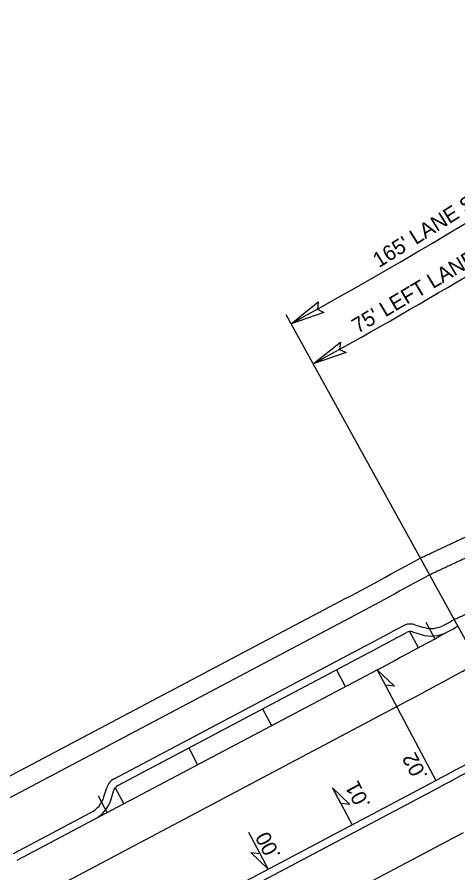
# Model space of a CAD drawing. Extents: x 1486489 to 1490134, y 497089 to 500876.
# Drawn here: x 1488009.9 to 1488126, y 498502.1 to 498727.6 of the extents above; entities that cross this region are included whole.
import ezdxf

# ---------------------------------------------------------------- set-up
doc = ezdxf.new("R2010")
doc.units = 0
for name, color, linetype in [('Prop Horizontal Alignment Station Label', 7, 'Continuous'), ('Scratch_Level_3', 7, 'Continuous'), ('Scratch_Level_5', 7, 'Continuous'), ('Sheet Block Title CELL', 7, 'Continuous'), ('Sheet Border Standard 30in CELL', 7, 'Continuous'), ('Sheet Cutting Line CELL', 7, 'Continuous'), ('Sheet Plot Border Outside CELL', 7, 'Continuous'), ('Sheet Sticker Exception Certification CELL', 7, 'Continuous'), ('Sheet Title CELL', 7, 'Continuous')]:
    doc.layers.add(name, color=color, linetype=linetype)

msp = doc.modelspace()

# ---------------------------------------------------------------- linework, layer by layer
at = {"layer": 'Prop Horizontal Alignment Station Label'}
for p, q in [((1487895.85, 498468.22), (1488095.16, 498573.73)), ((1487898.19, 498463.8), (1488097.5, 498569.31)), ((1488077.52, 498486.32), (1488127.44, 498512.75))]:
    msp.add_line(p, q, dxfattribs=at)
for radius in [1432.5, 1437.5]:
    msp.add_arc((1487424.96, 499839.79), radius, 297.89497, 298.84598, dxfattribs=at)
for points in [[(1488116.08, 498585.03), (1488116.74, 498585.34), (1488117.4, 498585.64), (1488118.05, 498585.95), (1488118.71, 498586.25), (1488119.36, 498586.56), (1488120.02, 498586.87), (1488120.67, 498587.17), (1488121.33, 498587.48), (1488121.98, 498587.79), (1488122.64, 498588.1), (1488123.29, 498588.4), (1488123.95, 498588.71), (1488124.6, 498589.02), (1488125.26, 498589.33), (1488125.91, 498589.64), (1488126.57, 498589.95), (1488127.22, 498590.26), (1488127.87, 498590.57), (1488128.53, 498590.88), (1488129.18, 498591.2), (1488129.83, 498591.51), (1488130.49, 498591.82), (1488131.14, 498592.13), (1488131.79, 498592.45), (1488132.45, 498592.76), (1488133.1, 498593.07), (1488133.75, 498593.39), (1488134.4, 498593.7), (1488135.06, 498594.01), (1488135.71, 498594.33), (1488136.36, 498594.65), (1488137.01, 498594.96), (1488137.66, 498595.28), (1488138.32, 498595.59), (1488138.97, 498595.91), (1488139.62, 498596.23), (1488140.27, 498596.54), (1488140.92, 498596.86), (1488141.57, 498597.18), (1488142.22, 498597.5), (1488142.87, 498597.82), (1488143.52, 498598.14), (1488144.18, 498598.46), (1488144.83, 498598.77), (1488145.48, 498599.09), (1488146.13, 498599.42), (1488146.78, 498599.74), (1488147.43, 498600.06), (1488148.07, 498600.38), (1488148.72, 498600.7), (1488149.37, 498601.02), (1488150.02, 498601.34), (1488150.67, 498601.67), (1488151.32, 498601.99), (1488151.97, 498602.31), (1488152.62, 498602.64), (1488153.27, 498602.96), (1488153.91, 498603.29), (1488154.56, 498603.61), (1488155.21, 498603.94), (1488155.86, 498604.26), (1488156.51, 498604.59), (1488157.15, 498604.91), (1488157.8, 498605.24), (1488158.45, 498605.57), (1488159.1, 498605.89), (1488159.74, 498606.22), (1488160.39, 498606.55), (1488161.04, 498606.88), (1488161.68, 498607.21), (1488162.33, 498607.54), (1488162.98, 498607.86), (1488163.62, 498608.19), (1488164.27, 498608.52)], [(1488118.5, 498580.65), (1488119.15, 498580.96), (1488119.81, 498581.26), (1488120.47, 498581.57), (1488121.13, 498581.88), (1488121.79, 498582.19), (1488122.44, 498582.49), (1488123.1, 498582.8), (1488123.76, 498583.11), (1488124.42, 498583.42), (1488125.07, 498583.73), (1488125.73, 498584.04), (1488126.39, 498584.35), (1488127.04, 498584.66), (1488127.7, 498584.97), (1488128.36, 498585.28), (1488129.01, 498585.59), (1488129.67, 498585.9), (1488130.33, 498586.22), (1488130.98, 498586.53), (1488131.64, 498586.84), (1488132.29, 498587.15), (1488132.95, 498587.47), (1488133.6, 498587.78), (1488134.26, 498588.1), (1488134.91, 498588.41), (1488135.57, 498588.72), (1488136.22, 498589.04), (1488136.88, 498589.36), (1488137.53, 498589.67), (1488138.19, 498589.99), (1488138.84, 498590.3), (1488139.5, 498590.62), (1488140.15, 498590.94), (1488140.8, 498591.26), (1488141.46, 498591.57), (1488142.11, 498591.89), (1488142.76, 498592.21), (1488143.42, 498592.53), (1488144.07, 498592.85), (1488144.72, 498593.17), (1488145.38, 498593.49), (1488146.03, 498593.81), (1488146.68, 498594.13), (1488147.33, 498594.45), (1488147.99, 498594.77), (1488148.64, 498595.09), (1488149.29, 498595.41), (1488149.94, 498595.74), (1488150.59, 498596.06), (1488151.25, 498596.38), (1488151.9, 498596.71), (1488152.55, 498597.03), (1488153.2, 498597.35), (1488153.85, 498597.68), (1488154.5, 498598), (1488155.15, 498598.33), (1488155.8, 498598.65), (1488156.45, 498598.98), (1488157.1, 498599.31), (1488157.75, 498599.63), (1488158.4, 498599.96), (1488159.05, 498600.29), (1488159.7, 498600.61), (1488160.35, 498600.94), (1488161, 498601.27), (1488161.65, 498601.6), (1488162.3, 498601.93), (1488162.95, 498602.26), (1488163.6, 498602.58), (1488164.25, 498602.91), (1488164.9, 498603.24), (1488165.55, 498603.58), (1488166.19, 498603.91), (1488166.84, 498604.24)]]:
    msp.add_spline(points, degree=3, dxfattribs=at)
at = {"layer": 'Scratch_Level_3'}
for p, q in [((1488104.76, 498555.62), (1488120.2, 498526.45)), ((1488092.95, 498524.48), (1488098.1, 498514.75)), ((1488070.86, 498512.78), (1488076, 498503.06))]:
    msp.add_line(p, q, dxfattribs=at)
for points in [[(1488104.76, 498555.62), (1488109.33, 498551.25), (1488106.92, 498551.53)], [(1488092.95, 498524.48), (1488097.53, 498520.11), (1488095.12, 498520.39)], [(1488076, 498503.06), (1488071.43, 498507.42), (1488073.84, 498507.14)]]:
    msp.add_lwpolyline(points, close=True, dxfattribs=at)
at = {"layer": 'Scratch_Level_5'}
for p, q in [((1488114.6, 498567.48), (1488116.89, 498566.78)), ((1488035.47, 498526.86), (1488101.48, 498561.8)), ((1487850.46, 498381.4), (1488121.13, 498524.68)), ((1488032.78, 498522.1), (1488033.52, 498524.5)), ((1488008.99, 498507.18), (1488029.36, 498517.97))]:
    msp.add_line(p, q, dxfattribs=at)
for centre, radius, start, end in [((1487424.96, 499839.79), 1451, 298.7239, 298.84598), ((1487424.96, 499839.79), 1446, 297.89497, 298.34679), ((1488113.44, 498563.66), 4, 72.9972, 118.3468), ((1488118.94, 498573.48), 7, 252.9972, 298.7239), ((1487424.96, 499839.79), 1488, 297.89497, 299.86952), ((1488037.34, 498523.32), 4, 117.895, 162.895), ((1488026.09, 498524.15), 7, 297.895, 342.895)]:
    msp.add_arc(centre, radius, start, end, dxfattribs=at)
msp.add_spline([(1488125.01, 498568.83), (1488125.67, 498569.14), (1488126.34, 498569.45), (1488127, 498569.76), (1488127.67, 498570.07), (1488128.33, 498570.38), (1488128.99, 498570.69), (1488129.66, 498571), (1488130.32, 498571.31), (1488130.98, 498571.62), (1488131.65, 498571.94), (1488132.31, 498572.25), (1488132.97, 498572.56), (1488133.63, 498572.88), (1488134.3, 498573.19), (1488134.96, 498573.51), (1488135.62, 498573.82), (1488136.28, 498574.13), (1488136.95, 498574.45), (1488137.61, 498574.77), (1488138.27, 498575.08), (1488138.93, 498575.4), (1488139.59, 498575.72), (1488140.25, 498576.03), (1488140.91, 498576.35), (1488141.58, 498576.67), (1488142.24, 498576.99), (1488142.9, 498577.3), (1488143.56, 498577.62), (1488144.22, 498577.94), (1488144.88, 498578.26), (1488145.54, 498578.58), (1488146.2, 498578.9), (1488146.86, 498579.22), (1488147.52, 498579.54), (1488148.18, 498579.87), (1488148.27, 498579.91)], degree=3, dxfattribs=at)
at = {"layer": 'Sheet Block Title CELL'}
for p, q in [((1488030.3, 498516.2), (1488104.75, 498555.61)), ((1488094, 498555.58), (1488096.34, 498551.16)), ((1487839.23, 498402.61), (1488109.9, 498545.89)), ((1488074.56, 498545.29), (1488076.9, 498540.87)), ((1488055.12, 498535), (1488057.45, 498530.58))]:
    msp.add_line(p, q, dxfattribs=at)
for radius, end in [(1453, 298.7239), (1464, 298.84598)]:
    msp.add_arc((1487424.96, 499839.79), radius, 297.89497, end, dxfattribs=at)
at = {"layer": 'Sheet Border Standard 30in CELL'}
for p, q in [((1488117.54, 498568.15), (1488119.93, 498563.76)), ((1488115.6, 498561.41), (1488113.22, 498565.81)), ((1488035.67, 498524.7), (1488038.01, 498520.28)), ((1488031.25, 498522.36), (1488033.59, 498517.94))]:
    msp.add_line(p, q, dxfattribs=at)
at = {"layer": 'Sheet Cutting Line CELL'}
msp.add_line((1488130.32, 498559.19), (1488080.79, 498649.11), dxfattribs=at)
for radius, end in [(1361.98, 305.25533), (1374.09, 302.73044)]:
    msp.add_arc((1487424.96, 499839.79), radius, 298.84598, end, dxfattribs=at)
at = {"layer": 'Sheet Plot Border Outside CELL'}
for points in [[(1488090.69, 498649.78), (1488082.06, 498646.8), (1488089.22, 498652.57), (1488088.98, 498650.61)], [(1488096.53, 498639.18), (1488087.9, 498636.19), (1488095.06, 498641.96), (1488094.82, 498640)]]:
    msp.add_lwpolyline(points, close=True, dxfattribs=at)
at = {"layer": 'Sheet Sticker Exception Certification CELL'}
for p, q in [((1488114.02, 498565.57), (1488116.3, 498564.87)), ((1488036.4, 498525.09), (1488102.41, 498560.03)), ((1487849.52, 498383.17), (1488120.19, 498526.45)), ((1488034.69, 498521.51), (1488035.43, 498523.91)), ((1488009.93, 498505.42), (1488030.3, 498516.2))]:
    msp.add_line(p, q, dxfattribs=at)
for centre, radius, start, end in [((1487424.96, 499839.79), 1453, 298.7239, 298.84598), ((1487424.96, 499839.79), 1448, 297.89497, 298.34679), ((1488113.44, 498563.66), 2, 72.9972, 118.3468), ((1488118.94, 498573.48), 9, 252.9972, 298.7239), ((1487424.96, 499839.79), 1486, 297.89497, 299.86952), ((1488037.34, 498523.32), 2, 117.895, 162.895), ((1488026.09, 498524.15), 9, 297.895, 342.895)]:
    msp.add_arc(centre, radius, start, end, dxfattribs=at)

# ---------------------------------------------------------------- texts
at = {"layer": 'Scratch_Level_3'}
for s, p in [('.02', (1488118.14, 498527.62)), ('.01', (1488103.1, 498520.11)), ('.00', (1488079.45, 498506.76))]:
    msp.add_text(s, height=4, rotation=117.895, dxfattribs=at).set_placement(p)
at = {"layer": 'Sheet Title CELL'}
for s, rotation, p in [("165' LANE SHIFT & MEDIAN TAPER", 32.0377, (1488105.18, 498661.43)), ("75' LEFT LANE TAPER", 30.7882, (1488099.61, 498644.12))]:
    msp.add_text(s, height=4, rotation=rotation, dxfattribs=at).set_placement(p)

doc.saveas('drawing.dxf')
